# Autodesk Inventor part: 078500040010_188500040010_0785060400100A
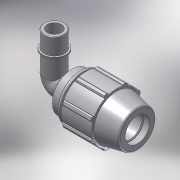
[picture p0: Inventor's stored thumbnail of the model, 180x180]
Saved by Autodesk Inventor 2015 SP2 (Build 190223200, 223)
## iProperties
Created: 2017-02
Part Number: 078500040010_188500040010_0785060400100A
Material: PVC-Piping
Description: PLASSON 90° ELBOW MALE ADAPTOR 40-1"
Document SubType Name: Modeling
Designer: KIM
Mass: 92.6774 g
Surface Area: 199.44 cm^2
Volume: 66.1981 cm^3
Density: 1.4 g/cm^3
Appearance: Smooth - White
Author: KIM
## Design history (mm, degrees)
derived "07850.ipt"
feature "Solid1::07850.ipt"
tag "TaggingFeature1"
body "Solid1"
other parameters: "d4" = 10.33333, "d5" = 31, "d7" = 82, "d9" = 17.71429, "d11" = 4.13333, "d13" = 120 deg, "d14" = 56, "d15" = 12 deg, "d16" = 71.34, "d18" = 2, "d19" = 35 deg, "d20" = 17.5 deg, "d21" = 76.26, "d23" = 0, "d25" = 360 deg, "d27" = 1.64, "d33" = 0.8, "d42" = 45.88, "d43" = 2.46, "d46" = 1.2, "d51" = 124, "d68" = 4.13333, "d73" = 33.249, "d75" = 38.23635, "d76" = 23.2743, "d77" = 22, "d79" = 13.2996, "d80" = 0.99747, "d83" = 0, "d84" = 0, "d91" = 61.5, "d93" = 84, "d94" = 33.249, "d95" = 23.2743, "d96" = 12.4, "d97" = 50 deg, "E_" = 82, "A_" = 124, "l_" = 84, "R_" = 33.249
